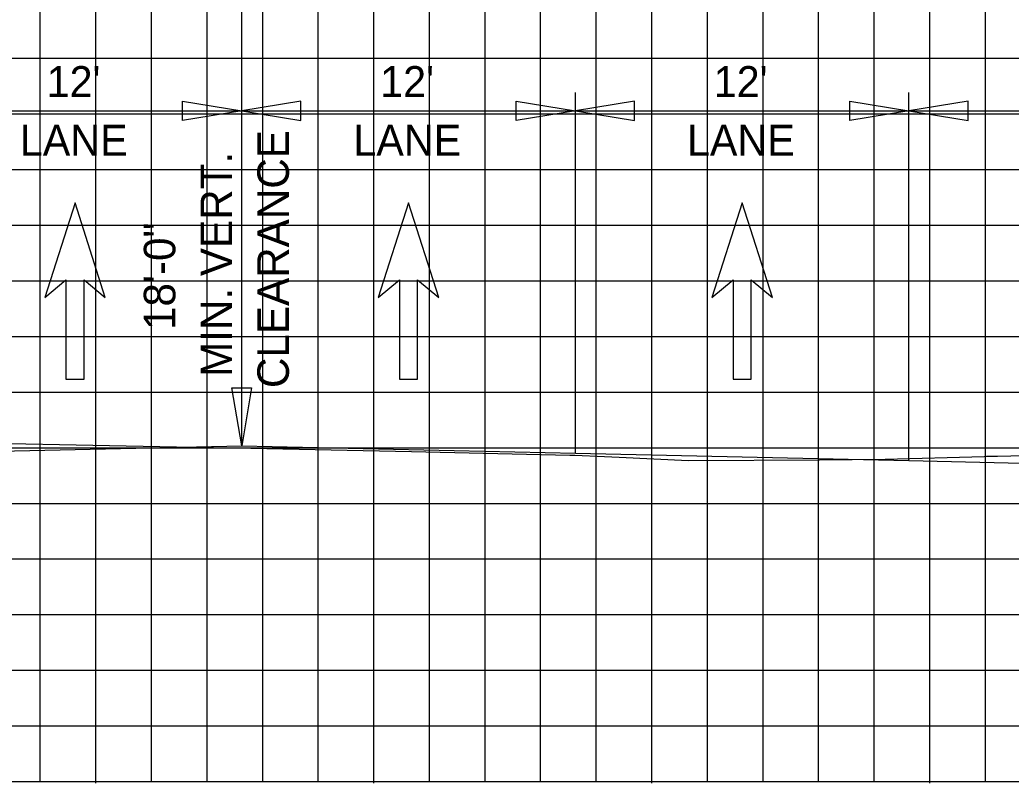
# Model space of a CAD drawing. Extents: x 2193008 to 2198143, y 1236112 to 1237864.
# Drawn here: x 2195761.97 to 2195797.63, y 1237163.05 to 1237190.49 of the extents above; entities that cross this region are included whole.
import ezdxf

# ---------------------------------------------------------------- set-up
doc = ezdxf.new("R2010")
doc.units = 0
for name, color, linetype in [('3', 7, 'Continuous'), ('60', 7, 'Continuous'), ('GSDIMS', 7, 'Continuous'), ('Level 28', 7, 'Continuous'), ('Level 55', 7, 'Continuous'), ('M-ROADS', 7, 'Continuous')]:
    doc.layers.add(name, color=color, linetype=linetype)

msp = doc.modelspace()

# ---------------------------------------------------------------- linework, layer by layer
at = {"layer": '3'}
for p, q in [((2195769.956, 1237175.172), (2195769.956, 1237193.172)), ((2195769.956, 1237175.172), (2195769.956, 1237187.876)), ((2195781.956, 1237174.908), (2195781.956, 1237187.876)), ((2195793.956, 1237174.644), (2195793.956, 1237187.876))]:
    msp.add_line(p, q, dxfattribs=at)
at = {"layer": '60'}
for p, q in [((2195734.707, 1237163.106), (2195864.707, 1237163.106)), ((2195764.707, 1237163.046), (2195764.707, 1237163.106)), ((2195774.707, 1237163.046), (2195774.707, 1237163.106)), ((2195784.707, 1237163.046), (2195784.707, 1237163.106)), ((2195794.707, 1237163.046), (2195794.707, 1237163.106))]:
    msp.add_line(p, q, dxfattribs=at)
for points in [[(2195737.201, 1237174.078), (2195747.956, 1237174.508), (2195757.956, 1237174.908), (2195769.956, 1237175.172), (2195781.956, 1237174.908), (2195793.956, 1237174.644)], [(2195793.956, 1237174.644), (2195817.956, 1237174.084), (2195833.456, 1237173.464)]]:
    msp.add_lwpolyline(points, dxfattribs=at)
at = {"layer": 'GSDIMS'}
for p, q in [((2195757.956, 1237187.214), (2195769.956, 1237187.214)), ((2195769.956, 1237187.214), (2195781.956, 1237187.214)), ((2195781.956, 1237187.214), (2195793.956, 1237187.214)), ((2195793.956, 1237187.214), (2195805.956, 1237187.214))]:
    msp.add_line(p, q, dxfattribs=at)
for points in [[(2195769.956, 1237187.214), (2195767.827, 1237186.867), (2195767.827, 1237187.561)], [(2195769.956, 1237187.214), (2195772.084, 1237186.867), (2195772.084, 1237187.561)], [(2195781.956, 1237187.214), (2195779.827, 1237186.867), (2195779.827, 1237187.561)], [(2195781.956, 1237187.214), (2195784.084, 1237186.867), (2195784.084, 1237187.561)], [(2195793.956, 1237187.214), (2195791.827, 1237186.867), (2195791.827, 1237187.561)], [(2195793.956, 1237187.214), (2195796.084, 1237186.867), (2195796.084, 1237187.561)], [(2195769.956, 1237175.172), (2195769.601, 1237177.255), (2195770.31, 1237177.255)]]:
    msp.add_lwpolyline(points, close=True, dxfattribs=at)
at = {"layer": 'Level 28'}
for p, q in [((2195763.956, 1237183.904), (2195762.866, 1237180.506)), ((2195765.045, 1237180.506), (2195763.956, 1237183.904)), ((2195775.956, 1237183.904), (2195774.866, 1237180.506)), ((2195777.045, 1237180.506), (2195775.956, 1237183.904)), ((2195787.956, 1237183.904), (2195786.866, 1237180.506)), ((2195789.045, 1237180.506), (2195787.956, 1237183.904)), ((2195762.866, 1237180.506), (2195763.629, 1237181.146)), ((2195763.629, 1237181.146), (2195763.629, 1237177.575)), ((2195764.282, 1237177.575), (2195764.282, 1237181.146)), ((2195764.282, 1237181.146), (2195765.045, 1237180.506)), ((2195774.866, 1237180.506), (2195775.629, 1237181.146)), ((2195775.629, 1237181.146), (2195775.629, 1237177.575)), ((2195776.282, 1237177.575), (2195776.282, 1237181.146)), ((2195776.282, 1237181.146), (2195777.045, 1237180.506)), ((2195786.866, 1237180.506), (2195787.629, 1237181.146)), ((2195787.629, 1237181.146), (2195787.629, 1237177.575)), ((2195788.282, 1237177.575), (2195788.282, 1237181.146)), ((2195788.282, 1237181.146), (2195789.045, 1237180.506)), ((2195763.629, 1237177.575), (2195764.282, 1237177.575)), ((2195775.629, 1237177.575), (2195776.282, 1237177.575)), ((2195787.629, 1237177.575), (2195788.282, 1237177.575))]:
    msp.add_line(p, q, dxfattribs=at)
at = {"layer": 'M-ROADS'}
for p, q in [((2195762.707, 1237163.106), (2195762.707, 1237223.106)), ((2195764.707, 1237163.106), (2195764.707, 1237223.106)), ((2195766.707, 1237163.106), (2195766.707, 1237223.106)), ((2195768.707, 1237163.106), (2195768.707, 1237223.106)), ((2195770.707, 1237163.106), (2195770.707, 1237223.106)), ((2195772.707, 1237163.106), (2195772.707, 1237223.106)), ((2195774.707, 1237163.106), (2195774.707, 1237223.106)), ((2195776.707, 1237163.106), (2195776.707, 1237223.106)), ((2195778.707, 1237163.106), (2195778.707, 1237223.106)), ((2195780.707, 1237163.106), (2195780.707, 1237223.106)), ((2195782.707, 1237163.106), (2195782.707, 1237223.106)), ((2195784.707, 1237163.106), (2195784.707, 1237223.106)), ((2195786.707, 1237163.106), (2195786.707, 1237223.106)), ((2195788.707, 1237163.106), (2195788.707, 1237223.106)), ((2195790.707, 1237163.106), (2195790.707, 1237223.106)), ((2195792.707, 1237163.106), (2195792.707, 1237223.106)), ((2195794.707, 1237163.106), (2195794.707, 1237223.106)), ((2195796.707, 1237163.106), (2195796.707, 1237223.106)), ((2195734.707, 1237189.106), (2195864.707, 1237189.106)), ((2195734.707, 1237187.106), (2195864.707, 1237187.106)), ((2195734.707, 1237185.106), (2195864.707, 1237185.106)), ((2195734.707, 1237183.106), (2195864.707, 1237183.106)), ((2195734.707, 1237181.106), (2195864.707, 1237181.106)), ((2195734.707, 1237179.106), (2195864.707, 1237179.106)), ((2195734.707, 1237177.106), (2195864.707, 1237177.106)), ((2195734.707, 1237175.106), (2195864.707, 1237175.106)), ((2195734.707, 1237173.106), (2195864.707, 1237173.106)), ((2195734.707, 1237171.106), (2195864.707, 1237171.106)), ((2195734.707, 1237169.106), (2195864.707, 1237169.106)), ((2195734.707, 1237167.106), (2195864.707, 1237167.106)), ((2195734.707, 1237165.106), (2195864.707, 1237165.106)), ((2195734.707, 1237163.106), (2195864.707, 1237163.106))]:
    msp.add_line(p, q, dxfattribs=at)
msp.add_lwpolyline([(2195734.707, 1237175.255), (2195739.205, 1237175.305), (2195745.917, 1237175.393), (2195750.848, 1237175.365), (2195757.963, 1237175.325), (2195767.602, 1237175.142), (2195770.281, 1237175.092), (2195776.061, 1237174.965), (2195781.761, 1237174.84), (2195781.931, 1237174.832), (2195783.005, 1237174.789), (2195783.53, 1237174.764), (2195786.029, 1237174.641), (2195790.74, 1237174.676), (2195793.097, 1237174.69), (2195796.662, 1237174.794), (2195796.744, 1237174.796), (2195797.143, 1237174.806), (2195805.244, 1237175.008)], dxfattribs=at)

# ---------------------------------------------------------------- texts
at = {"layer": 'Level 55'}
for s, p in [("12'", (2195762.934, 1237187.714)), ("12'", (2195774.934, 1237187.714)), ("12'", (2195786.934, 1237187.714)), ('LANE', (2195761.97, 1237185.604)), ('LANE', (2195773.97, 1237185.604)), ('LANE', (2195785.97, 1237185.604))]:
    msp.add_text(s, height=1.1105, dxfattribs=at).set_placement(p)
for s, p in [('CLEARANCE', (2195771.65, 1237177.25)), ('MIN. VERT.', (2195769.607, 1237177.65)), ('18\'-0"', (2195767.565, 1237179.337))]:
    msp.add_text(s, height=1.1346, rotation=90, dxfattribs=at).set_placement(p)

doc.saveas('drawing.dxf')
